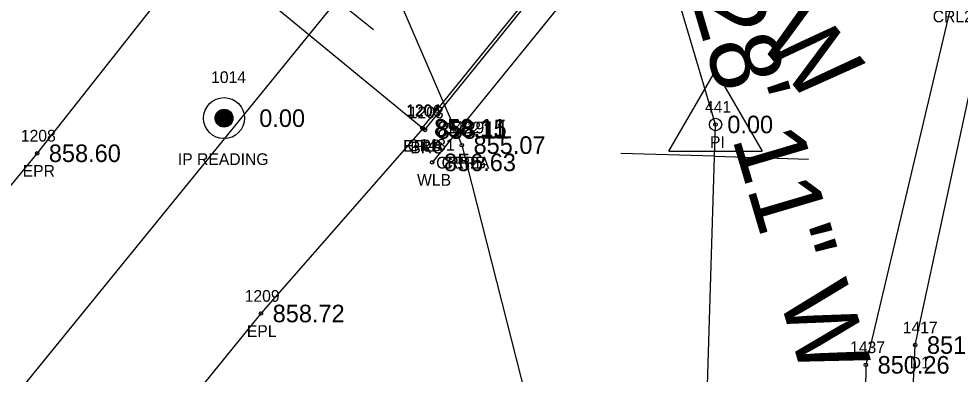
# Model space of a CAD drawing. Extents: x 1448136 to 1453623, y 1125056 to 1128842.
# Drawn here: x 1450680.5 to 1450760.7, y 1126902.1 to 1126932.5 of the extents above; entities that cross this region are included whole.
import ezdxf

# ---------------------------------------------------------------- set-up
doc = ezdxf.new("R2010")
doc.units = 0
for name, color, linetype in [('RD_EX_Bridge', 7, 'Continuous'), ('RD_EX_Bridge_txCode', 7, 'Continuous'), ('RD_EX_Driveway', 7, 'Continuous'), ('RD_EX_Driveway_txCode', 7, 'Continuous'), ('RD_EX_DV_Prop_txCode', 7, 'Continuous'), ('RD_EX_DV_PropPin', 7, 'Continuous'), ('RD_EX_GuardRail', 7, 'Continuous'), ('RD_EX_GuardRail_txCode', 7, 'Continuous'), ('RD_EX_H2O', 7, 'Continuous'), ('RD_EX_H2O_txCode', 7, 'Continuous'), ('RD_EX_Road', 7, 'Continuous'), ('RD_EX_Road_txCode', 7, 'Continuous'), ('RD_EX_TX_Bridge_ELEV', 7, 'Continuous'), ('RD_EX_TX_Driveway_ELEV', 7, 'Continuous'), ('RD_EX_TX_DV_Prop_ELEV', 7, 'Continuous'), ('RD_EX_TX_GuardRail_ELEV', 7, 'Continuous'), ('RD_EX_TX_H2O_ELEV', 7, 'Continuous'), ('RD_EX_TX_Road_ELEV', 7, 'Continuous'), ('RD_EX_TX_UT_ELEV', 7, 'Continuous'), ('RD_EX_UT', 7, 'Continuous'), ('RD_EX_UT_txCode', 7, 'Continuous'), ('RD_HC_Cl', 7, 'Continuous'), ('RD_HC_Data', 7, 'Continuous'), ('RD_HC_Data_Tic', 7, 'Continuous'), ('RD_HC_Survey_ELEV', 7, 'Continuous'), ('RD_HC_txCode', 7, 'Continuous'), ('RD_SMD_Locator', 7, 'Continuous')]:
    doc.layers.add(name, color=color, linetype=linetype)

msp = doc.modelspace()

# ---------------------------------------------------------------- linework, layer by layer
at = {"layer": 'RD_EX_Bridge'}
msp.add_lwpolyline([(1450752.682, 1126969.491), (1450732.61, 1126985.852), (1450695.205, 1126939.422), (1450715.121, 1126922.991), (1450752.682, 1126969.491)], dxfattribs=at)
at = {"layer": 'RD_EX_Driveway'}
msp.add_lwpolyline([(1450755.319, 1126870.088), (1450756.908, 1126904.63), (1450765.178, 1126943.07), (1450766.814, 1126971.057), (1450764.578, 1126975.925), (1450758.819, 1126979.051), (1450762.34, 1126983.686)], dxfattribs=at)
at = {"layer": 'RD_EX_DV_PropPin'}
for p, q in [((1450697.82, 1126923.26), (1450697.82, 1126924.741)), ((1450697.855, 1126923.253), (1450697.855, 1126924.749)), ((1450697.89, 1126923.247), (1450697.89, 1126924.755)), ((1450697.925, 1126923.243), (1450697.925, 1126924.759)), ((1450697.96, 1126923.241), (1450697.96, 1126924.761)), ((1450697.995, 1126923.24), (1450697.995, 1126924.762)), ((1450698.03, 1126923.241), (1450698.03, 1126924.761)), ((1450698.065, 1126923.243), (1450698.065, 1126924.759)), ((1450698.1, 1126923.247), (1450698.1, 1126924.755)), ((1450698.135, 1126923.253), (1450698.135, 1126924.749)), ((1450698.17, 1126923.26), (1450698.17, 1126924.741)), ((1450697.259, 1126923.805), (1450697.259, 1126924.197)), ((1450697.294, 1126923.703), (1450697.294, 1126924.299)), ((1450697.329, 1126923.631), (1450697.329, 1126924.37)), ((1450697.364, 1126923.574), (1450697.364, 1126924.427)), ((1450697.399, 1126923.527), (1450697.399, 1126924.475)), ((1450697.434, 1126923.486), (1450697.434, 1126924.516)), ((1450697.469, 1126923.45), (1450697.469, 1126924.552)), ((1450697.504, 1126923.419), (1450697.504, 1126924.583)), ((1450697.539, 1126923.391), (1450697.539, 1126924.611)), ((1450697.575, 1126923.366), (1450697.575, 1126924.635)), ((1450697.61, 1126923.344), (1450697.61, 1126924.657)), ((1450697.645, 1126923.325), (1450697.645, 1126924.676)), ((1450697.68, 1126923.308), (1450697.68, 1126924.694)), ((1450697.715, 1126923.293), (1450697.715, 1126924.708)), ((1450697.75, 1126923.28), (1450697.75, 1126924.721)), ((1450697.785, 1126923.269), (1450697.785, 1126924.732)), ((1450698.205, 1126923.269), (1450698.205, 1126924.732)), ((1450698.24, 1126923.28), (1450698.24, 1126924.721)), ((1450698.275, 1126923.293), (1450698.275, 1126924.708)), ((1450698.31, 1126923.308), (1450698.31, 1126924.694)), ((1450698.345, 1126923.325), (1450698.345, 1126924.676)), ((1450698.38, 1126923.344), (1450698.38, 1126924.657)), ((1450698.415, 1126923.366), (1450698.415, 1126924.635)), ((1450698.45, 1126923.391), (1450698.45, 1126924.611)), ((1450698.485, 1126923.419), (1450698.485, 1126924.583)), ((1450698.52, 1126923.45), (1450698.52, 1126924.552)), ((1450698.555, 1126923.486), (1450698.555, 1126924.516)), ((1450698.59, 1126923.527), (1450698.59, 1126924.475)), ((1450698.625, 1126923.574), (1450698.625, 1126924.427)), ((1450698.66, 1126923.631), (1450698.66, 1126924.37)), ((1450698.695, 1126923.703), (1450698.695, 1126924.299)), ((1450698.73, 1126923.805), (1450698.73, 1126924.197))]:
    msp.add_line(p, q, dxfattribs=at)
for radius in [1.75, 0.761]:
    msp.add_circle((1450697.995, 1126924.001), radius, dxfattribs=at)
at = {"layer": 'RD_EX_GuardRail'}
msp.add_line((1450752.477, 1126969.723), (1450714.894, 1126923.178), dxfattribs=at)
at = {"layer": 'RD_EX_H2O'}
for points in [[(1450790.266, 1127617.477), (1450787.405, 1127572.488), (1450770.56, 1127562.94), (1450759.958, 1127503.293), (1450769.343, 1127461.296), (1450745.953, 1127442.744), (1450719.185, 1127377.134), (1450706.091, 1127312.949), (1450685.565, 1127238.741), (1450684.415, 1127163.983), (1450689.617, 1127099.648), (1450700.631, 1127049.817), (1450721.694, 1127031.115), (1450714.056, 1127011.463), (1450690.923, 1126980.716), (1450694.809, 1126968.037), (1450702.956, 1126957.215), (1450718.262, 1126921.701)], [(1450745.696, 1126955.228), (1450760.074, 1126934.183), (1450752.702, 1126902.942), (1450751.991, 1126845.751), (1450749.838, 1126753.839), (1450765.552, 1126601.502), (1450766.355, 1126534.456), (1450772.788, 1126478.952), (1450780.128, 1126423.057)], [(1450718.262, 1126921.701), (1450723.733, 1126900.098), (1450722.534, 1126842.544), (1450724.681, 1126757.518), (1450723.652, 1126673.102), (1450740.735, 1126600.368), (1450742.256, 1126535.959), (1450738.155, 1126478.884), (1450753.626, 1126426.156)]]:
    msp.add_lwpolyline(points, dxfattribs=at)
at = {"layer": 'RD_EX_Road'}
for points in [[(1450696.026, 1126938.745), (1450682.061, 1126921.003), (1450652.28, 1126884.75), (1450619.837, 1126847.491), (1450585.671, 1126813.189), (1450567.697, 1126796.905), (1450549.636, 1126781.657), (1450510.035, 1126752.98), (1450468.429, 1126728.625), (1450425.524, 1126707.881), (1450379.552, 1126690.085), (1450334.806, 1126677.215), (1450288.338, 1126667.766)], [(1450714.95, 1126923.132), (1450701.14, 1126907.324), (1450669.786, 1126868.734), (1450636.796, 1126831.171), (1450601.851, 1126795.928), (1450563.907, 1126763.205), (1450523.613, 1126734.271), (1450480.523, 1126708.448), (1450435.582, 1126686.641), (1450388.584, 1126668.752), (1450340.734, 1126655.015), (1450291.741, 1126645.329)]]:
    msp.add_lwpolyline(points, dxfattribs=at)
at = {"layer": 'RD_EX_UT'}
msp.add_line((1450754.936, 1126968.645), (1450715.739, 1126920.227), dxfattribs=at)
at = {"layer": 'RD_HC_Cl'}
for p, q in [((1450930.039, 1127207.931), (1450648.853, 1126861.726)), ((1450739.888, 1126923.462), (1450735.332, 1126938.873)), ((1450734.484, 1126750.596), (1450739.888, 1126923.462))]:
    msp.add_line(p, q, dxfattribs=at)
at = {"layer": 'RD_HC_Data'}
for p, q in [((1450735.917, 1126921.169), (1450739.889, 1126928.049)), ((1450739.889, 1126928.049), (1450743.858, 1126921.169)), ((1450735.917, 1126921.169), (1450743.858, 1126921.169))]:
    msp.add_line(p, q, dxfattribs=at)
msp.add_circle((1450739.888, 1126923.462), 0.529, dxfattribs=at)
at = {"layer": 'RD_HC_Data_Tic'}
for p, q in [((1450707.617, 1126934.078), (1450710.722, 1126931.556)), ((1450739.803, 1126920.742), (1450731.807, 1126920.992)), ((1450739.803, 1126920.742), (1450747.799, 1126920.492))]:
    msp.add_line(p, q, dxfattribs=at)
at = {"layer": 'RD_SMD_Locator'}
for centre in [(1450697.995, 1126924.001), (1450714.894, 1126923.178), (1450714.95, 1126923.132), (1450715.121, 1126922.991), (1450739.888, 1126923.462), (1450718.262, 1126921.701), (1450718.262, 1126921.701), (1450682.061, 1126921.003), (1450715.739, 1126920.227), (1450701.14, 1126907.324), (1450756.908, 1126904.63), (1450752.702, 1126902.942)]:
    msp.add_circle(centre, 0.15, dxfattribs=at)

# ---------------------------------------------------------------- texts
at = {"layer": 'RD_EX_Bridge_txCode'}
for s, p in [('1203', (1450713.736, 1126923.991)), ('BRC', (1450713.869, 1126920.991))]:
    msp.add_text(s, height=1, dxfattribs=at).set_placement(p)
at = {"layer": 'RD_EX_Driveway_txCode'}
for s, p in [('1417', (1450755.845, 1126905.63)), ('D1', (1450756.435, 1126902.63))]:
    msp.add_text(s, height=1, dxfattribs=at).set_placement(p)
at = {"layer": 'RD_EX_DV_Prop_txCode'}
for s, p in [('1014', (1450696.892, 1126927.001)), ('IP READING', (1450694.058, 1126920.001))]:
    msp.add_text(s, height=1, dxfattribs=at).set_placement(p)
at = {"layer": 'RD_EX_GuardRail_txCode'}
for s, p in [('1204', (1450713.508, 1126924.178)), ('GRB', (1450713.642, 1126921.178))]:
    msp.add_text(s, height=1, dxfattribs=at).set_placement(p)
at = {"layer": 'RD_EX_H2O_txCode'}
for s, p in [('CRL2', (1450758.397, 1126932.183)), ('1432', (1450716.915, 1126922.701)), ('1719', (1450717.199, 1126922.701)), ('CRR2A', (1450716.073, 1126919.701)), ('CRRB', (1450716.537, 1126919.701)), ('1437', (1450751.356, 1126903.942))]:
    msp.add_text(s, height=1, dxfattribs=at).set_placement(p)
at = {"layer": 'RD_EX_Road_txCode'}
for s, p in [('1206', (1450713.541, 1126924.132)), ('1208', (1450680.675, 1126922.003)), ('EPLA', (1450713.257, 1126921.132)), ('EPR', (1450680.833, 1126919.003)), ('1209', (1450699.755, 1126908.324)), ('EPL', (1450699.936, 1126905.324))]:
    msp.add_text(s, height=1, dxfattribs=at).set_placement(p)
at = {"layer": 'RD_EX_TX_Bridge_ELEV'}
msp.add_text('858.11', height=1.5, dxfattribs=at).set_placement((1450716.121, 1126922.241))
at = {"layer": 'RD_EX_TX_Driveway_ELEV'}
msp.add_text('851.07', height=1.5, dxfattribs=at).set_placement((1450757.908, 1126903.88))
at = {"layer": 'RD_EX_TX_DV_Prop_ELEV'}
msp.add_text('0.00', height=1.5, dxfattribs=at).set_placement((1450700.995, 1126923.251))
at = {"layer": 'RD_EX_TX_GuardRail_ELEV'}
msp.add_text('858.11', height=1.5, dxfattribs=at).set_placement((1450715.894, 1126922.428))
at = {"layer": 'RD_EX_TX_H2O_ELEV'}
for s, p in [('855.07', (1450719.262, 1126920.951)), ('855.07', (1450719.262, 1126920.951)), ('850.26', (1450753.702, 1126902.192))]:
    msp.add_text(s, height=1.5, dxfattribs=at).set_placement(p)
at = {"layer": 'RD_EX_TX_Road_ELEV'}
for s, p in [('858.15', (1450715.95, 1126922.382)), ('858.60', (1450683.061, 1126920.253)), ('858.72', (1450702.14, 1126906.574))]:
    msp.add_text(s, height=1.5, dxfattribs=at).set_placement(p)
at = {"layer": 'RD_EX_TX_UT_ELEV'}
msp.add_text('856.63', height=1.5, dxfattribs=at).set_placement((1450716.739, 1126919.477))
at = {"layer": 'RD_EX_UT_txCode'}
for s, p in [('1431', (1450714.676, 1126921.227)), ('WLB', (1450714.447, 1126918.227))]:
    msp.add_text(s, height=1, dxfattribs=at).set_placement(p)
at = {"layer": 'RD_HC_Data'}
for s, rotation, p in [('N 39%%d 17\' 35" W', 309.29306, (1450712.192, 1126968.731)), ('N 16%%d 28\' 11" W', 286.46986, (1450731.329, 1126955.939))]:
    msp.add_text(s, height=6, rotation=rotation, dxfattribs=at).set_placement(p)
at = {"layer": 'RD_HC_Survey_ELEV'}
msp.add_text('0.00', height=1.5, dxfattribs=at).set_placement((1450740.888, 1126922.712))
at = {"layer": 'RD_HC_txCode'}
for s, p in [('441', (1450738.99, 1126924.462)), ('PI', (1450739.415, 1126921.462))]:
    msp.add_text(s, height=1, dxfattribs=at).set_placement(p)

doc.saveas('drawing.dxf')
